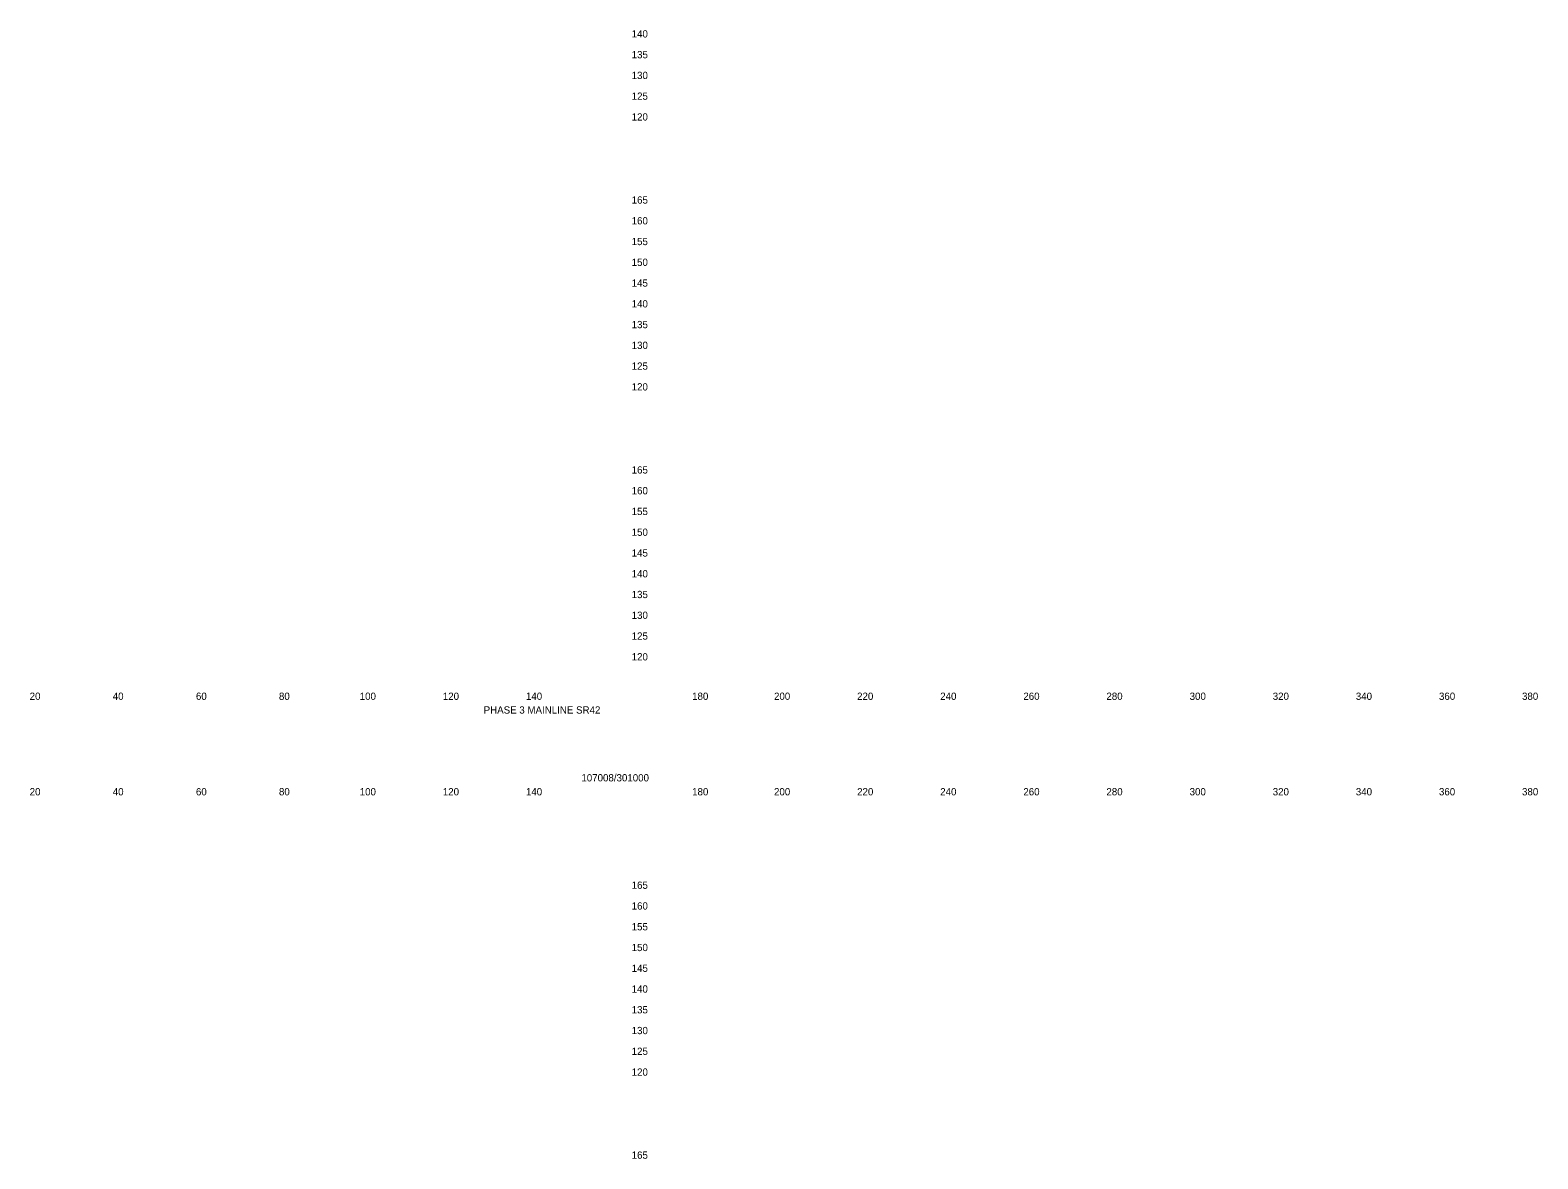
# Model space of a CAD drawing. Extents: x 21281 to 22024, y 6472 to 15198.
# Drawn here: x 21661.4 to 22024.2, y 7284.8 to 7556.6 of the extents above; entities that cross this region are included whole.
import ezdxf

# ---------------------------------------------------------------- set-up
doc = ezdxf.new("R2010")
doc.units = 0
doc.layers.add('Draft_XS_Grid', color=7, linetype='Continuous')
doc.layers.add('Draft_XS_Text', color=7, linetype='Continuous')

msp = doc.modelspace()

# ---------------------------------------------------------------- texts
at = {"layer": 'Draft_XS_Grid'}
for s, p in [('  140  ', (21804.84, 7554.84)), ('  135  ', (21804.84, 7549.84)), ('  130  ', (21804.84, 7544.84)), ('  125  ', (21804.84, 7539.84)), ('  120  ', (21804.84, 7534.84)), ('  165  ', (21804.84, 7514.84)), ('  160  ', (21804.84, 7509.84)), ('  155  ', (21804.84, 7504.84)), ('  150  ', (21804.84, 7499.84)), ('  145  ', (21804.84, 7494.84)), ('  140  ', (21804.84, 7489.84)), ('  135  ', (21804.84, 7484.84)), ('  130  ', (21804.84, 7479.84)), ('  125  ', (21804.84, 7474.84)), ('  120  ', (21804.84, 7469.84)), ('  165  ', (21804.84, 7449.84)), ('  160  ', (21804.84, 7444.84)), ('  155  ', (21804.84, 7439.84)), ('  150  ', (21804.84, 7434.84)), ('  145  ', (21804.84, 7429.84)), ('  140  ', (21804.84, 7424.84)), ('  135  ', (21804.84, 7419.84)), ('  130  ', (21804.84, 7414.84)), ('  125  ', (21804.84, 7409.84)), ('  120  ', (21804.84, 7404.84)), ('  165  ', (21804.84, 7349.84)), ('  160  ', (21804.84, 7344.84)), ('  155  ', (21804.84, 7339.84)), ('  150  ', (21804.84, 7334.84)), ('  145  ', (21804.84, 7329.84)), ('  140  ', (21804.84, 7324.84)), ('  135  ', (21804.84, 7319.84)), ('  130  ', (21804.84, 7314.84)), ('  125  ', (21804.84, 7309.84)), ('  120  ', (21804.84, 7304.84)), ('  165  ', (21804.84, 7284.84))]:
    msp.add_text(s, height=1.75, dxfattribs=at).set_placement(p)
at = {"layer": 'Draft_XS_Text'}
for s, p in [('  20  ', (21659.95, 7395.34)), ('  40  ', (21679.95, 7395.34)), ('  60  ', (21699.97, 7395.34)), ('  80  ', (21719.95, 7395.34)), ('  100  ', (21739.39, 7395.34)), ('  120  ', (21759.39, 7395.34)), ('  140  ', (21779.39, 7395.34)), ('  180  ', (21819.39, 7395.34)), ('  200  ', (21839.1, 7395.34)), ('  220  ', (21859.1, 7395.34)), ('  240  ', (21879.1, 7395.34)), ('  260  ', (21899.11, 7395.34)), ('  280  ', (21919.1, 7395.34)), ('  300  ', (21939.13, 7395.34)), ('  320  ', (21959.13, 7395.34)), ('  340  ', (21979.13, 7395.34)), ('  360  ', (21999.14, 7395.34)), ('  380  ', (22019.13, 7395.34)), ('PHASE 3 MAINLINE SR42', (21770.52, 7392.03)), ('107008/301000', (21794.04, 7375.7)), ('  20  ', (21659.95, 7372.34)), ('  40  ', (21679.95, 7372.34)), ('  60  ', (21699.97, 7372.34)), ('  80  ', (21719.95, 7372.34)), ('  100  ', (21739.39, 7372.34)), ('  120  ', (21759.39, 7372.34)), ('  140  ', (21779.39, 7372.34)), ('  180  ', (21819.39, 7372.34)), ('  200  ', (21839.1, 7372.34)), ('  220  ', (21859.1, 7372.34)), ('  240  ', (21879.1, 7372.34)), ('  260  ', (21899.11, 7372.34)), ('  280  ', (21919.1, 7372.34)), ('  300  ', (21939.13, 7372.34)), ('  320  ', (21959.13, 7372.34)), ('  340  ', (21979.13, 7372.34)), ('  360  ', (21999.14, 7372.34)), ('  380  ', (22019.13, 7372.34))]:
    msp.add_text(s, height=1.75, dxfattribs=at).set_placement(p)

doc.saveas('drawing.dxf')
